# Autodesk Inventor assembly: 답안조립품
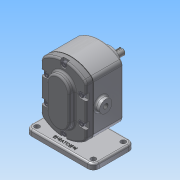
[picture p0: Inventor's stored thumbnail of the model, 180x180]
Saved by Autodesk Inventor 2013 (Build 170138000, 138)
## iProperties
Created: 2019-03
Part Number: 답안조립품
Document SubType Name: Assembly
Designer: Administrator
Author: Administrator
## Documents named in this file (11)
- C:\Users\Administrator\Desktop\490307V1010\답안조립품.iam
- C:\Users\Administrator\Desktop\490307V1010\본체.ipt
- C:\Users\Administrator\Desktop\490307V1010\개스킷.ipt
- C:\Users\Administrator\Desktop\490307V1010\메인축.ipt
- C:\Users\Administrator\Desktop\490307V1010\베어링부시.ipt
- C:\Users\Administrator\Desktop\490307V1010\볼트 M5.ipt
- C:\Users\Administrator\Desktop\490307V1010\서브축.ipt
- C:\Users\Administrator\Desktop\490307V1010\스퍼기어.ipt
- C:\Users\Administrator\Desktop\490307V1010\오일 실 16 28 7.ipt
- C:\Users\Administrator\Desktop\490307V1010\커버.ipt
- C:\Users\Administrator\Desktop\490307V1010\키 6 x 6 x 18.ipt
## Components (1 placed, 1 different names)
1. 개스킷:1
